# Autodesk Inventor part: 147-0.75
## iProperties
Created: 2007-06
Part Number: 147-0.75
Document SubType Name: Modeling
Designer: btaylor
Density: 1 g/cm^3
Author: btaylor
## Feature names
1. Extrusion1
2. Extrusion2
3. Chamfer2
4. Revolution1
5. Fillet2
6. Fillet3
7. Chamfer3
